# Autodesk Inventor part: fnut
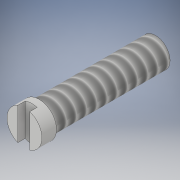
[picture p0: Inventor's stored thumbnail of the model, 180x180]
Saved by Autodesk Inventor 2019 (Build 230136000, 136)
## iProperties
Created: 2020-03
Part Number: fnut
Material: Generic
Document SubType Name: Modeling
Designer: ash
Density: 1 g/cm^3
Appearance: Default
Author: ash
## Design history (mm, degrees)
sketch "Sketch1"
  geometry: L1 (0, 4.671)-(1.2, 4.671); L2 (1.2, 4.671)-(1.2, 3.671); L3 (1.2, 3.671)-(1, 3.671); L4 (1, 3.671)-(1, -4.329); L5 (1, -4.329)-(0, -4.329); L6 (0, -4.329)-(0, 4.671); 1 further point
  constraints: 12 end point, 3 perpendicular, 2 horizontal, 1 vertical
  dimensions: "d0" = 1.2 distance of L1.start L1.end; "d1" = 1 distance of L1.end L2.end; "d2" = 0.2 distance of L2.end L3.end; "d3" = 8 distance of L3.end L4.end; "d9" = 1 distance of L4.end L5.end (derived)
revolve "Revolution1" sketch "Sketch1" stored, may be unused: angle "d4" = 90 deg
thread "Thread1" dims "d5" = 10, "d6" = 0
sketch "Sketch2"
  geometry: L1 (-0.456, 1.689)-(0.365, 1.689); L2 (0.365, 1.689)-(0.365, -1.734); L3 (0.365, -1.734)-(-0.456, -1.734); L4 (-0.456, -1.734)-(-0.456, 1.689); 1 further point
  constraints: 8 end point, 2 parallel, 1 horizontal, 1 perpendicular
extrude "Extrusion1" cut sketch "Sketch2" distance "d7" = 0.5; taper "d8" = 0 deg
sketch "Sketch3"
  geometry: 1 further point
body "Solid1"
